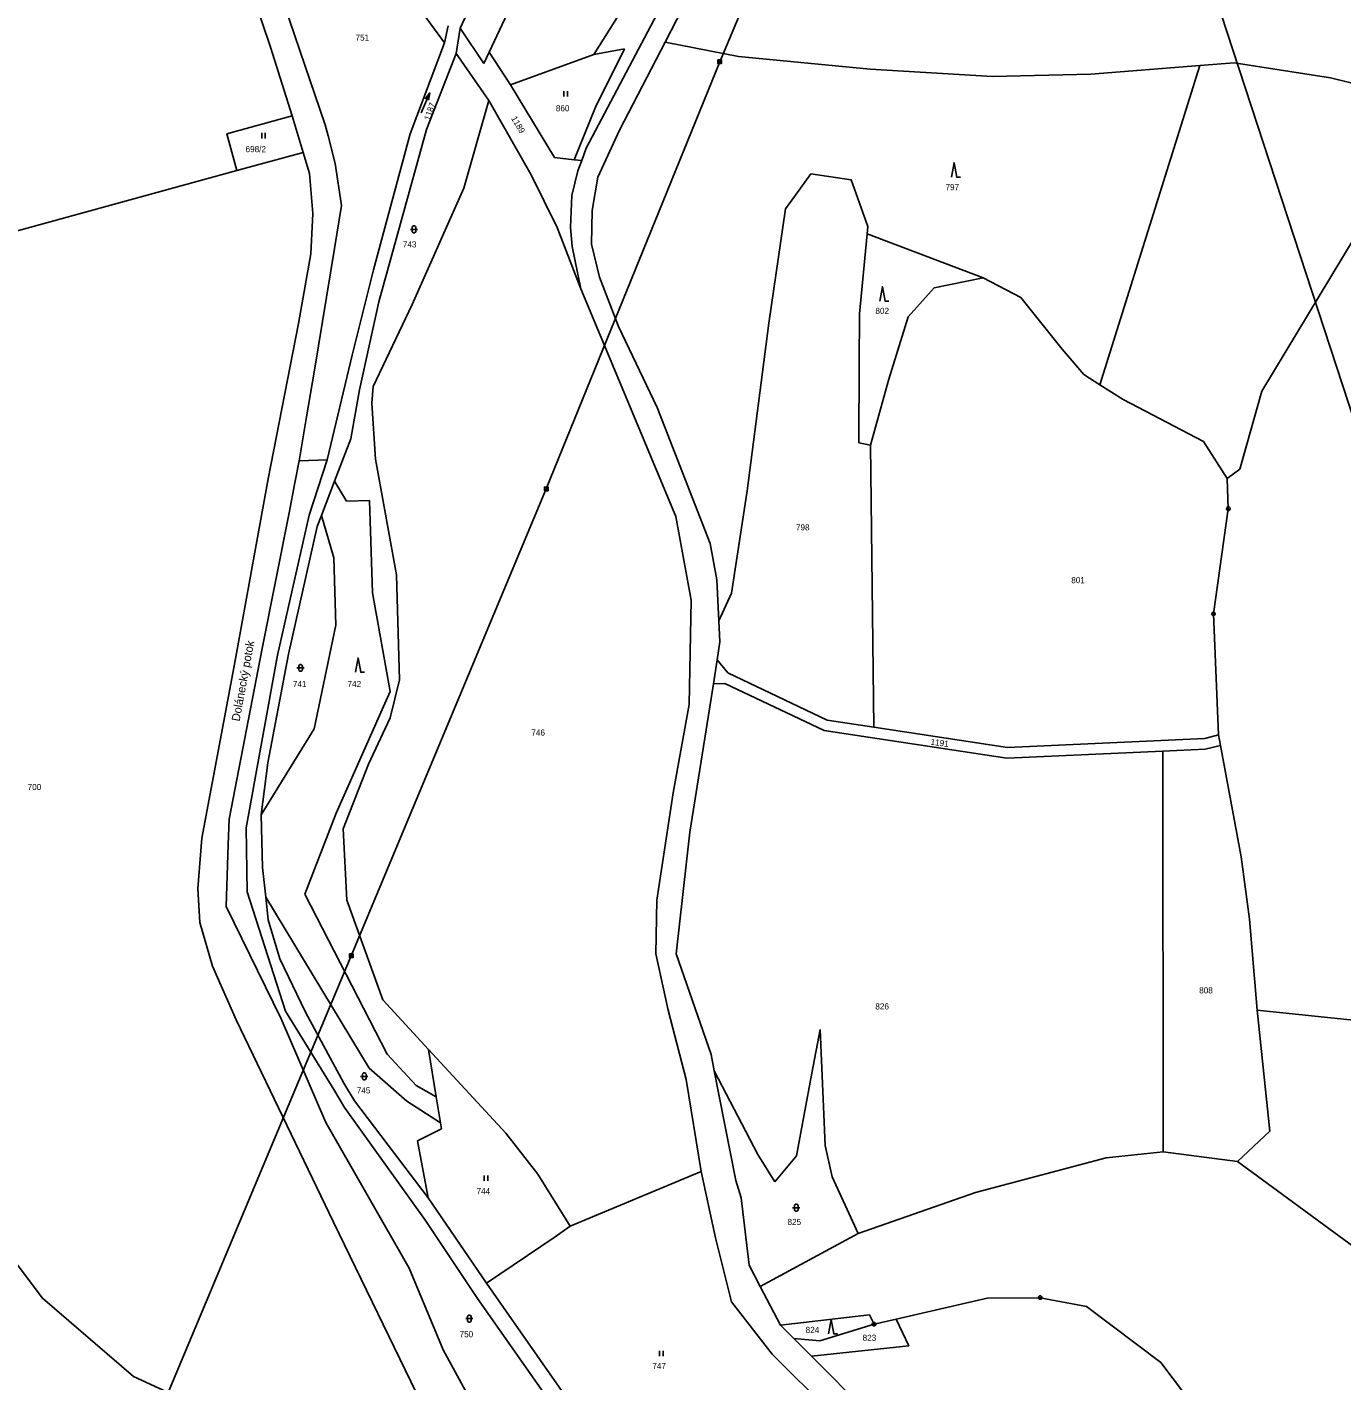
# Model space of a CAD drawing. Extents: x -812394 to -807601, y -1013098 to -1009266.
# Drawn here: x -809418.3 to -809052.3, y -1011158.1 to -1010781.2 of the extents above; entities that cross this region are included whole.
import ezdxf

# ---------------------------------------------------------------- set-up
doc = ezdxf.new("R2010")
doc.units = 0
for name, color, linetype in [('KN_HRANICE', 7, 'Continuous'), ('KN_KULTURY', 7, 'Continuous'), ('KN_MEZNIKY', 7, 'Continuous'), ('KN_PARCELY', 7, 'Continuous'), ('KN_VEDENI', 7, 'Continuous')]:
    doc.layers.add(name, color=color, linetype=linetype)

# ---------------------------------------------------------------- blocks, each defined once
blk = doc.blocks.new('306')
for p, q in [((-0.5, 1.5), (-0.5, 0)), ((0.5, 0), (0.5, 1.5))]:
    blk.add_line(p, q)
blk = doc.blocks.new('308')
blk.add_lwpolyline([(-0.75, 0), (0, 4), (0.75, 0), (1.75, 0)])
blk = doc.blocks.new('316')
for points in [[(-1, 1), (0.27, 1), (1, 1)], [(-0.5, 1.5), (-0.4, 1.79), (-0.15, 1.97), (0.16, 1.97), (0.41, 1.79), (0.51, 1.5), (0.51, 0.5), (0.41, 0.21), (0.16, 0.03), (-0.15, 0.03), (-0.4, 0.21), (-0.5, 0.5), (-0.5, 1.5)]]:
    blk.add_lwpolyline(points)
blk = doc.blocks.new('802')
blk.add_line((-3, 0), (3, 0))
blk.add_lwpolyline([(1, 0.5), (3, 0), (1, -0.5)])
blk = doc.blocks.new('105')
blk.add_line((-0.12, 0), (0.12, 0))
blk.add_lwpolyline([(0.15, 0.48), (0.4, 0.3), (0.5, 0.01), (0.4, -0.28), (0.15, -0.46), (-0.16, -0.46), (-0.41, -0.28), (-0.51, 0.01), (-0.41, 0.3), (-0.16, 0.48), (0.15, 0.48)])
blk = doc.blocks.new('602')
blk.add_lwpolyline([(-0.5, 0.5), (0.5, 0.5), (0.5, -0.5), (-0.5, -0.5), (-0.5, 0.5), (-0.44, 0.44), (0.44, 0.44), (0.44, 0.36), (-0.44, 0.36), (-0.44, 0.28), (0.44, 0.28), (0.44, 0.2), (-0.44, 0.2), (-0.44, 0.12), (0.44, 0.12), (0.44, 0.04), (-0.44, 0.04), (-0.44, -0.04), (0.44, -0.04), (0.44, -0.12), (-0.44, -0.12), (-0.44, -0.2), (0.44, -0.2), (0.44, -0.28), (-0.44, -0.28), (-0.44, -0.36), (0.44, -0.36), (0.44, -0.44), (-0.44, -0.44)])

msp = doc.modelspace()

# ---------------------------------------------------------------- linework, layer by layer
at = {"layer": 'KN_HRANICE'}
for p, q in [((-809212.01, -1010718.89), (-809262.62, -1010814.93)), ((-809350.5, -1010786.79), (-809360.9, -1010755.91)), ((-809260.51, -1010788.84), (-809238.67, -1010754.07)), ((-809287.3, -1010759.01), (-809297.76, -1010781.54)), ((-809278.14, -1010763.62), (-809289.64, -1010788.2)), ((-809240.68, -1010785.42), (-809232.78, -1010770.16)), ((-809312.31, -1010771.66), (-809302.07, -1010785.66)), ((-809302.07, -1010785.66), (-809301.09, -1010780.94)), ((-809297.76, -1010781.54), (-809298.85, -1010788.58)), ((-809291.14, -1010791.4), (-809297.76, -1010781.54)), ((-809311.7, -1010810.97), (-809302.07, -1010785.66)), ((-809253.38, -1010809.96), (-809240.68, -1010785.42)), ((-809220.26, -1010789.46), (-809240.68, -1010785.42)), ((-809346.14, -1010800.65), (-809350.5, -1010786.79)), ((-809298.85, -1010788.58), (-809307.08, -1010809.79)), ((-809298.85, -1010788.58), (-809289.73, -1010801.7)), ((-809289.64, -1010788.2), (-809291.14, -1010791.4)), ((-809283.71, -1010797.35), (-809289.64, -1010788.2)), ((-809283.71, -1010797.35), (-809260.51, -1010788.84)), ((-809260.51, -1010788.84), (-809252.02, -1010787.31)), ((-809260.08, -1010803.57), (-809252.02, -1010787.31)), ((-809183.63, -1010792.94), (-809220.26, -1010789.46)), ((-809149.52, -1010795.02), (-809183.63, -1010792.94)), ((-809091.8, -1010791.95), (-809122.15, -1010794.33)), ((-809119.63, -1010880.82), (-809091.8, -1010791.95)), ((-809082.28, -1010791.2), (-809091.8, -1010791.95)), ((-809055.45, -1010795.34), (-809082.28, -1010791.2)), ((-809271.44, -1010817.56), (-809283.71, -1010797.35)), ((-809122.15, -1010794.33), (-809149.52, -1010795.02)), ((-809029.02, -1010801.9), (-809055.45, -1010795.34)), ((-809344.54, -1010805.97), (-809346.14, -1010800.65)), ((-809289.73, -1010801.7), (-809296.75, -1010826.06)), ((-809289.73, -1010801.7), (-809277.95, -1010822.39)), ((-809265.96, -1010818.15), (-809260.08, -1010803.57)), ((-809341.48, -1010816.14), (-809344.54, -1010805.97)), ((-809321.83, -1010848.82), (-809311.7, -1010810.97)), ((-809307.08, -1010809.79), (-809320.4, -1010857.76)), ((-809259.44, -1010823.03), (-809253.38, -1010809.96)), ((-809341.48, -1010816.14), (-809359.87, -1010821.19)), ((-809339.72, -1010821.99), (-809341.48, -1010816.14)), ((-809262.62, -1010814.93), (-809263.88, -1010818.37)), ((-809265.96, -1010818.15), (-809271.44, -1010817.56)), ((-809263.88, -1010818.37), (-809265.96, -1010818.15)), ((-809264.94, -1010821.27), (-809263.88, -1010818.37)), ((-809359.87, -1010821.19), (-809492.16, -1010857.54)), ((-809338.73, -1010833.11), (-809339.72, -1010821.99)), ((-809277.95, -1010822.39), (-809270.78, -1010837.06)), ((-809266.62, -1010828.14), (-809264.94, -1010821.27)), ((-809260.97, -1010832.29), (-809259.44, -1010823.03)), ((-809296.75, -1010826.06), (-809311.13, -1010858.5)), ((-809267.01, -1010837.04), (-809266.62, -1010828.14)), ((-809204.66, -1010828.39), (-809207.16, -1010831.81)), ((-809339.33, -1010844.32), (-809338.73, -1010833.11)), ((-809261.18, -1010841.69), (-809260.97, -1010832.29)), ((-809207.16, -1010831.81), (-809211.78, -1010863.69)), ((-809045.32, -1010834.15), (-809074.57, -1010882.59)), ((-809270.78, -1010837.06), (-809264.15, -1010854.13)), ((-809266.59, -1010842.31), (-809267.01, -1010837.04)), ((-809152.12, -1010851.01), (-809184.46, -1010838.79)), ((-809264.15, -1010854.13), (-809266.59, -1010842.31)), ((-809258.97, -1010850.83), (-809261.18, -1010841.69)), ((-809342.76, -1010863.71), (-809339.33, -1010844.32)), ((-809327.78, -1010872.52), (-809321.83, -1010848.82)), ((-809253.7, -1010864.58), (-809258.97, -1010850.83)), ((-809152.12, -1010851.01), (-809141.63, -1010856.55)), ((-809320.4, -1010857.76), (-809325.74, -1010882.17)), ((-809264.15, -1010854.13), (-809237.69, -1010917.44)), ((-809141.63, -1010856.55), (-809130.13, -1010870.93)), ((-809311.13, -1010858.5), (-809321.92, -1010881.25)), ((-809351.15, -1010907.01), (-809342.76, -1010863.71)), ((-809242.93, -1010887.17), (-809253.7, -1010864.58)), ((-809211.78, -1010863.69), (-809217.85, -1010910.29)), ((-809334.79, -1010901.69), (-809327.78, -1010872.52)), ((-809130.13, -1010870.93), (-809124.17, -1010877.95)), ((-809124.17, -1010877.95), (-809119.63, -1010880.82)), ((-809325.74, -1010882.17), (-809328.19, -1010895.88)), ((-809321.92, -1010881.25), (-809322.29, -1010885.89)), ((-809119.63, -1010880.82), (-809113.21, -1010884.87)), ((-809074.57, -1010882.59), (-809080.73, -1010904.26)), ((-809322.29, -1010885.89), (-809321.27, -1010901.54)), ((-809228.17, -1010924.96), (-809242.93, -1010887.17)), ((-809113.21, -1010884.87), (-809090.86, -1010896.55)), ((-809340.51, -1010889.72), (-809342.56, -1010901.99)), ((-809328.19, -1010895.88), (-809332.71, -1010907.64)), ((-809183.47, -1010897.59), (-809186.8, -1010896.95)), ((-809182.59, -1010976.12), (-809183.47, -1010897.59)), ((-809090.86, -1010896.55), (-809084.22, -1010906.93)), ((-809342.56, -1010901.99), (-809343.75, -1010908.11)), ((-809342.56, -1010901.99), (-809334.79, -1010901.69)), ((-809339.74, -1010917.13), (-809334.79, -1010901.69)), ((-809321.27, -1010901.54), (-809315.42, -1010933.7)), ((-809080.73, -1010904.26), (-809084.22, -1010906.93)), ((-809360.75, -1010959.55), (-809351.15, -1010907.01)), ((-809332.71, -1010907.64), (-809336.38, -1010917.18)), ((-809329.36, -1010913.21), (-809332.71, -1010907.64)), ((-809217.85, -1010910.29), (-809222.2, -1010938.83)), ((-809084.22, -1010906.93), (-809083.93, -1010915.3)), ((-809348.56, -1010956.1), (-809339.74, -1010917.13)), ((-809336.38, -1010917.18), (-809337.58, -1010920.29)), ((-809237.69, -1010917.44), (-809233.39, -1010940.77)), ((-809083.93, -1010915.3), (-809088.03, -1010944.58)), ((-809337.58, -1010920.29), (-809345.55, -1010955.82)), ((-809226.26, -1010935.05), (-809228.17, -1010924.96)), ((-809315.42, -1010933.7), (-809314.64, -1010962.96)), ((-809225.71, -1010946.53), (-809226.26, -1010935.05)), ((-809222.2, -1010938.83), (-809225.71, -1010946.53)), ((-809233.39, -1010940.77), (-809233.99, -1010969.84)), ((-809225.43, -1010952.31), (-809225.71, -1010946.53)), ((-809088.03, -1010944.58), (-809086.63, -1010978.22)), ((-809226.21, -1010957.33), (-809225.43, -1010952.31)), ((-809357.31, -1011004.14), (-809348.56, -1010956.1)), ((-809345.55, -1010955.82), (-809351.29, -1010986.02)), ((-809227.25, -1010964.08), (-809226.21, -1010957.33)), ((-809223.26, -1010961.02), (-809226.21, -1010957.33)), ((-809369.66, -1011006.98), (-809360.75, -1010959.55)), ((-809314.64, -1010962.96), (-809317.18, -1010973.46)), ((-809195.54, -1010974.17), (-809223.26, -1010961.02)), ((-809233.82, -1011005.3), (-809227.25, -1010964.08)), ((-809227.25, -1010964.08), (-809224.09, -1010963.94)), ((-809224.09, -1010963.94), (-809196.42, -1010977.07)), ((-809233.99, -1010969.84), (-809238.41, -1010994.42)), ((-809317.18, -1010973.46), (-809323.27, -1010986.38)), ((-809182.59, -1010976.12), (-809195.54, -1010974.17)), ((-809196.42, -1010977.07), (-809145.53, -1010984.73)), ((-809145.37, -1010981.72), (-809182.59, -1010976.12)), ((-809086.63, -1010978.22), (-809090.45, -1010979.23)), ((-809086.08, -1010981.18), (-809086.63, -1010978.22)), ((-809090.45, -1010979.23), (-809145.37, -1010981.72)), ((-809090.32, -1010982.23), (-809086.08, -1010981.18)), ((-809086.08, -1010981.18), (-809080.31, -1011012.17)), ((-809145.53, -1010984.73), (-809102.18, -1010982.77)), ((-809102.18, -1010982.77), (-809090.32, -1010982.23)), ((-809102.18, -1010982.77), (-809102.05, -1011094.31)), ((-809351.29, -1010986.02), (-809353.14, -1011000.49)), ((-809323.27, -1010986.38), (-809330.28, -1011004.43)), ((-809238.41, -1010994.42), (-809243.03, -1011024.27)), ((-809356.99, -1011021.98), (-809357.31, -1011004.14)), ((-809330.28, -1011004.43), (-809329.24, -1011024.22)), ((-809370.8, -1011021.05), (-809369.66, -1011006.98)), ((-809237.57, -1011039.2), (-809233.82, -1011005.3)), ((-809080.31, -1011012.17), (-809078.02, -1011029.54)), ((-809346.38, -1011055.16), (-809356.99, -1011021.98)), ((-809351.85, -1011023.44), (-809351.16, -1011029.72)), ((-809329.24, -1011024.22), (-809319.27, -1011052)), ((-809243.03, -1011024.27), (-809243.29, -1011039.21)), ((-809351.16, -1011029.72), (-809347.94, -1011040.55)), ((-809078.02, -1011029.54), (-809075.88, -1011054.83)), ((-809347.94, -1011040.55), (-809340.8, -1011055.43)), ((-809243.29, -1011039.21), (-809239.88, -1011054.88)), ((-809227.91, -1011067.2), (-809237.57, -1011039.2)), ((-809319.27, -1011052), (-809306.54, -1011065.84)), ((-809332.9, -1011076.93), (-809346.38, -1011055.16)), ((-809340.8, -1011055.43), (-809330.11, -1011075.2)), ((-809239.88, -1011054.88), (-809234.8, -1011074.21)), ((-809072.31, -1011088.53), (-809075.88, -1011054.83)), ((-809075.88, -1011054.83), (-808951.36, -1011068.01)), ((-809197.56, -1011060.27), (-809199.87, -1011072.38)), ((-809196.14, -1011092.51), (-809197.56, -1011060.27)), ((-809306.54, -1011065.84), (-809284.98, -1011089.13)), ((-809304.41, -1011078.99), (-809306.54, -1011065.84)), ((-809227.01, -1011071.76), (-809227.91, -1011067.2)), ((-809214.9, -1011095.05), (-809227.01, -1011071.76)), ((-809221.02, -1011102.26), (-809227.01, -1011071.76)), ((-809199.87, -1011072.38), (-809204.08, -1011095.41)), ((-809330.11, -1011075.2), (-809327.19, -1011080.12)), ((-809234.8, -1011074.21), (-809230.64, -1011099.78)), ((-809329.89, -1011082), (-809332.9, -1011076.93)), ((-809303.25, -1011086.19), (-809304.41, -1011078.99)), ((-809307.36, -1011113.45), (-809329.89, -1011082)), ((-809327.19, -1011080.12), (-809306.61, -1011107.09)), ((-809303.25, -1011086.19), (-809302.97, -1011087.89)), ((-809284.98, -1011089.13), (-809276.12, -1011100.51)), ((-809081.38, -1011096.96), (-809072.31, -1011088.53)), ((-809210.17, -1011102.63), (-809214.9, -1011095.05)), ((-809194.17, -1011101.23), (-809196.14, -1011092.51)), ((-809081.38, -1011096.96), (-809102.05, -1011094.31)), ((-809204.08, -1011095.41), (-809210.17, -1011102.63)), ((-809048.99, -1011120.76), (-809081.38, -1011096.96)), ((-809276.12, -1011100.51), (-809267.11, -1011114.96)), ((-809267.11, -1011114.96), (-809230.64, -1011099.78)), ((-809230.64, -1011099.78), (-809226.7, -1011118.26)), ((-809219.52, -1011107.12), (-809221.02, -1011102.26)), ((-809186.94, -1011117), (-809194.17, -1011101.23)), ((-809437.7, -1011103.69), (-809413.98, -1011135.02)), ((-809306.61, -1011107.09), (-809290.45, -1011130.86)), ((-809217.26, -1011125.81), (-809219.52, -1011107.12)), ((-809292.88, -1011135.16), (-809307.36, -1011113.45)), ((-809271.53, -1011118.12), (-809267.11, -1011114.96)), ((-809186.94, -1011117), (-809214.18, -1011131.75)), ((-809290.45, -1011130.86), (-809271.53, -1011118.12)), ((-809226.7, -1011118.26), (-809222.24, -1011136.1)), ((-809214.18, -1011131.75), (-809217.26, -1011125.81)), ((-809290.45, -1011130.86), (-809244.33, -1011196.74)), ((-809208.59, -1011142.51), (-809214.18, -1011131.75)), ((-809413.98, -1011135.02), (-809388.65, -1011156.86)), ((-809249.48, -1011196.8), (-809292.88, -1011135.16)), ((-809222.24, -1011136.1), (-809210.85, -1011150.65)), ((-809151.01, -1011135.04), (-809176.38, -1011140.9)), ((-809136.28, -1011134.9), (-809151.01, -1011135.04)), ((-809123.42, -1011137.33), (-809136.28, -1011134.9)), ((-809183.77, -1011139.63), (-809208.59, -1011142.51)), ((-809182.51, -1011142.31), (-809183.77, -1011139.63)), ((-809102.71, -1011152.94), (-809123.42, -1011137.33)), ((-809204.83, -1011146.28), (-809208.59, -1011142.51)), ((-809182.51, -1011142.31), (-809197.6, -1011146.91)), ((-809176.38, -1011140.9), (-809182.51, -1011142.31)), ((-809172.88, -1011148.32), (-809176.38, -1011140.9)), ((-809199.91, -1011151.21), (-809204.83, -1011146.28)), ((-809204.83, -1011146.28), (-809197.6, -1011146.91)), ((-809210.85, -1011150.65), (-809177.04, -1011184.11)), ((-809199.91, -1011151.21), (-809172.88, -1011148.32)), ((-809180.8, -1011170.37), (-809199.91, -1011151.21)), ((-809083.49, -1011178.16), (-809102.71, -1011152.94)), ((-809388.65, -1011156.86), (-809355.08, -1011172.25))]:
    msp.add_line(p, q, dxfattribs=at)
for points in [[(-809334.49, -1010811.54), (-809335.27, -1010808.48), (-809348.01, -1010771.1)], [(-809359.87, -1010821.19), (-809362.69, -1010810.95), (-809344.54, -1010805.97)], [(-809340.51, -1010889.72), (-809338.33, -1010876.69), (-809332.75, -1010842.86), (-809330.81, -1010830.91), (-809332.56, -1010819.17), (-809334.49, -1010811.54)], [(-809204.66, -1010828.39), (-809200.08, -1010822.13), (-809188.88, -1010823.74), (-809184.26, -1010836.72), (-809184.46, -1010838.79)], [(-809186.8, -1010896.95), (-809186.63, -1010874.99), (-809186.59, -1010861.1), (-809184.46, -1010838.79)], [(-809152.12, -1010851.01), (-809165.76, -1010853.83), (-809173.03, -1010861.88), (-809178.44, -1010879.24), (-809183.47, -1010897.59)], [(-809362.27, -1011008.78), (-809362.03, -1011001.71), (-809352.87, -1010954.23), (-809345.36, -1010916.43), (-809343.75, -1010908.11)], [(-809329.36, -1010913.21), (-809322.98, -1010913.02), (-809322.16, -1010938.75)], [(-809353.14, -1011000.49), (-809338.36, -1010976.54), (-809332.32, -1010947.69), (-809332.87, -1010928.98), (-809336.38, -1010917.18)], [(-809341.02, -1011022.61), (-809332.28, -1011000.05), (-809317.23, -1010966.13), (-809322.16, -1010938.75)], [(-809351.85, -1011023.44), (-809352.77, -1011015.12), (-809353.14, -1011000.49)], [(-809311.9, -1011126.69), (-809335.1, -1011086.13), (-809347.52, -1011057.28), (-809362.87, -1011025.99), (-809362.27, -1011008.78)], [(-809294.96, -1011192.54), (-809311.49, -1011158.23), (-809332.98, -1011113.92), (-809360.07, -1011057.57), (-809366.67, -1011042.66), (-809370.18, -1011030.46), (-809370.8, -1011021.05)], [(-809351.85, -1011023.44), (-809323.11, -1011070.98), (-809312.59, -1011080.19), (-809303.25, -1011086.19)], [(-809341.02, -1011022.61), (-809318.1, -1011067.16), (-809309.99, -1011075.82), (-809304.41, -1011078.99)], [(-809302.97, -1011087.89), (-809309.58, -1011091.26), (-809306.61, -1011107.09)], [(-809186.94, -1011117), (-809154.28, -1011105.63), (-809117.9, -1011095.99), (-809102.05, -1011094.31)], [(-809272.89, -1011193.49), (-809282.21, -1011186.49), (-809302.51, -1011149.43), (-809311.9, -1011126.69)]]:
    msp.add_lwpolyline(points, dxfattribs=at)
at = {"layer": 'KN_VEDENI'}
for points in [[(-809513.17, -1009474.26), (-809487.03, -1009553.9), (-809382.67, -1009871.8), (-809271.71, -1010210.69), (-809133.29, -1010632.77), (-809030.14, -1010947.95), (-808933.39, -1011241.46), (-808834.45, -1011543.27), (-808752.75, -1011794.76), (-808648.03, -1012113.89), (-808628.65, -1012173.95)], [(-808436.07, -1010405.5), (-808486.59, -1010412.34), (-808533.36, -1010418.3), (-808675.88, -1010426.28), (-808821.29, -1010438.46), (-808966.01, -1010451.39), (-809054.03, -1010611.07), (-809175.87, -1010672.9), (-809225.49, -1010790.89), (-809273.78, -1010909.78), (-809328.04, -1011039.73), (-809401.1, -1011213.98), (-809452.49, -1011335.08), (-809491.27, -1011432.33), (-809530.59, -1011529.94)]]:
    msp.add_lwpolyline(points, dxfattribs=at)

# ---------------------------------------------------------------- block references
at = {"layer": 'KN_KULTURY', "rotation": 66.062034}
msp.add_blockref('802', (-809307.4, -1010802.33), dxfattribs=at)
at = {"layer": 'KN_KULTURY'}
for name, p in [('306', (-809268.37, -1010800.54)), ('306', (-809352.48, -1010812.22)), ('308', (-809160.24, -1010823.02)), ('316', (-809310.6, -1010838.56)), ('308', (-809180.19, -1010857.51)), ('316', (-809342.18, -1010960.59)), ('308', (-809326.16, -1010960.82)), ('316', (-809324.45, -1011074.33)), ('306', (-809290.53, -1011102.4)), ('316', (-809204.19, -1011110.87)), ('316', (-809295.18, -1011141.73)), ('308', (-809194.47, -1011144.96)), ('306', (-809241.72, -1011151.16))]:
    msp.add_blockref(name, p, dxfattribs=at)
at = {"layer": 'KN_MEZNIKY'}
for p in [(-809083.93, -1010915.3), (-809088.03, -1010944.58), (-809136.28, -1011134.9), (-809182.51, -1011142.31)]:
    msp.add_blockref('105', p, dxfattribs=at)
at = {"layer": 'KN_VEDENI'}
for p in [(-809225.49, -1010790.89), (-809273.78, -1010909.78), (-809328.04, -1011039.73)]:
    msp.add_blockref('602', p, dxfattribs=at)

# ---------------------------------------------------------------- texts
at = {"layer": 'KN_PARCELY'}
for s, p in [('751', (-809326.87, -1010785.01)), ('860', (-809271.1, -1010804.68)), ('698/2', (-809357.48, -1010816.06)), ('797', (-809162.64, -1010826.64)), ('743', (-809313.7, -1010842.58)), ('802', (-809182.14, -1010861.09)), ('798', (-809204.27, -1010921.34)), ('801', (-809127.63, -1010936.03)), ('741', (-809344.29, -1010964.93)), ('742', (-809329.09, -1010964.93)), ('746', (-809277.92, -1010978.45)), ('700', (-809418.14, -1010993.61)), ('808', (-809092.02, -1011050.2)), ('826', (-809182.17, -1011054.68)), ('745', (-809326.52, -1011078.04)), ('744', (-809293.18, -1011106.11)), ('825', (-809206.62, -1011114.67)), ('824', (-809201.57, -1011144.72)), ('750', (-809297.9, -1011145.91)), ('823', (-809185.71, -1011146.91)), ('747', (-809244.23, -1011154.74))]:
    msp.add_text(s, height=1.7, dxfattribs=at).set_placement(p)
for s, height, rotation, p in [('1187', 1.7, 71.161, (-809306.22, -1010807.37)), ('1189', 1.7, 300.975, (-809283.61, -1010806.67)), ('Dolánecký potok', 2.3, 79.527, (-809359.15, -1010974.61)), ('1191', 1.7, 352.484, (-809166.87, -1010980.97))]:
    msp.add_text(s, height=height, rotation=rotation, dxfattribs=at).set_placement(p)

doc.saveas('drawing.dxf')
